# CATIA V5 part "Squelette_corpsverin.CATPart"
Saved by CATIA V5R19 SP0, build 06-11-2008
Part number: Squelette_corpsverin
Bounding box of the stored display mesh (mm): x -500 to 500, y -2391.774 to 1443.75, z -1458.497 to 134.485
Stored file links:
  C:\Users\Guillaume et Fanny\Documents\IFMA\2A\IAO\Squelette_corpsverin.CATPart
  C:\Users\Guillaume et Fanny\Documents\IFMA\2A\IAO\Train d'aterrissage.CATProduct
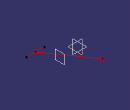
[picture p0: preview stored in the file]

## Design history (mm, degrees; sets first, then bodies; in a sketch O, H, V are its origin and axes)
Set1
  Point1: linked copy from another document
  Point2: linked copy from another document
Body1 (main body)
  Line1: type PtDir, Direction (1, 0, 0), Start -500, End 500, RefPoint Point1
  Line2: type PtPt, SecondPoint Point1, FirstPoint Point2
  Plane1: type Offset, Offset 1000, RefPlane yz-plane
